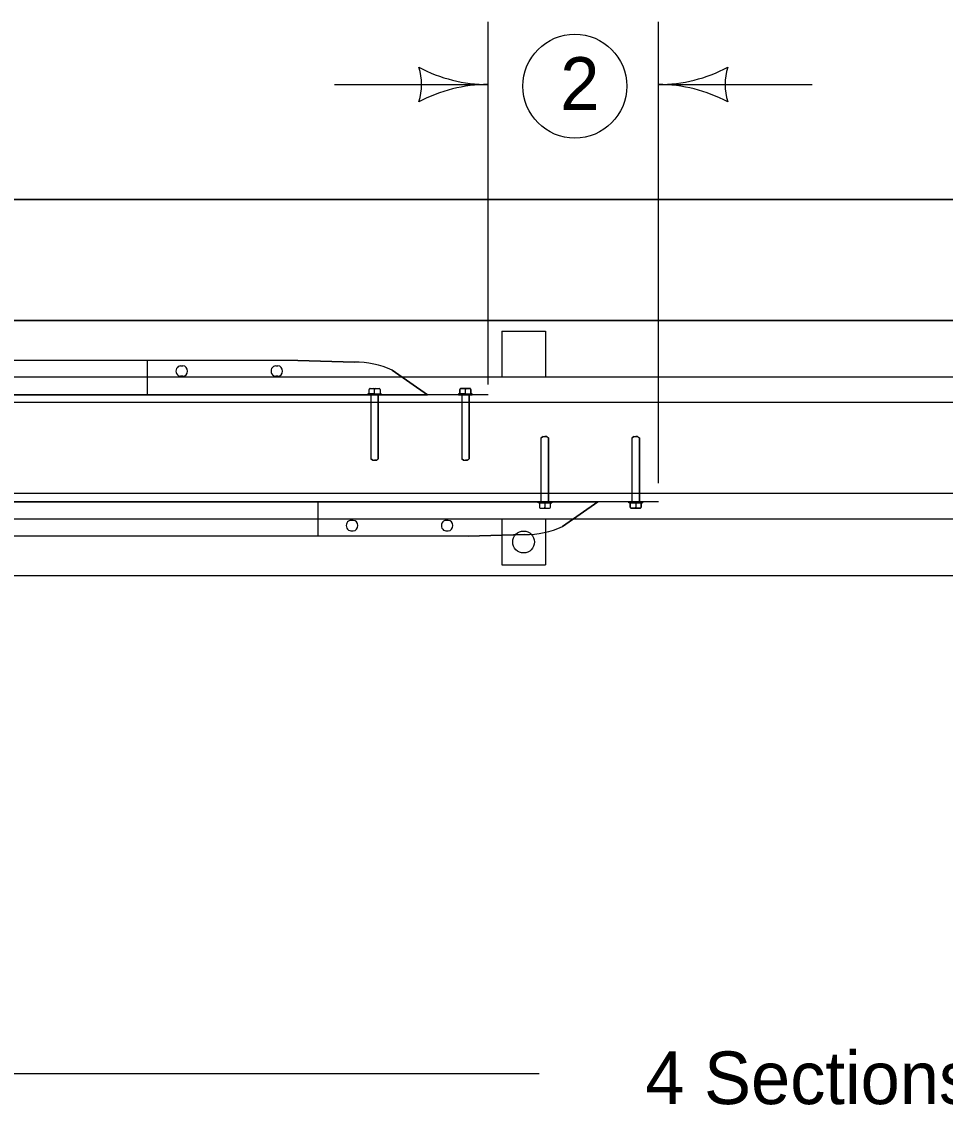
# Model space of a CAD drawing. Extents: x 10028 to 81668, y 3581 to 11018.
# Drawn here: x 21470.5 to 21736.9, y 8565.3 to 8882.3 of the extents above; entities that cross this region are included whole.
import ezdxf

# ---------------------------------------------------------------- set-up
doc = ezdxf.new("R2010")
doc.units = 0
for name, color, linetype in [('conPaving', 7, 'Continuous'), ('dsnCellsNorthArrow', 7, 'Continuous'), ('dsnTextTabulation', 7, 'Continuous'), ('Level 41', 7, 'Continuous'), ('Level 9', 7, 'Continuous')]:
    doc.layers.add(name, color=color, linetype=linetype)

msp = doc.modelspace()

# ---------------------------------------------------------------- linework, layer by layer
at = {"layer": 'conPaving'}
for p, q in [((21550.11, 8784.52), (21265.03, 8784.52)), ((21516.25, 8782.98), (21516.92, 8782.98)), ((21543.68, 8782.98), (21544.34, 8782.98)), ((21566.42, 8784.09), (21550.11, 8784.52)), ((21587.51, 8774.62), (21577.26, 8781.76)), ((21516.92, 8780.01), (21516.25, 8780.01)), ((21544.34, 8780.01), (21543.68, 8780.01)), ((21596.85, 8776.17), (21596.85, 8774.91)), ((21598.72, 8776.48), (21597.13, 8776.48)), ((21599.75, 8776.48), (21598.72, 8776.48)), ((21600.03, 8774.91), (21600.03, 8776.17)), ((21243.97, 8774.62), (21571.16, 8774.62)), ((21571.16, 8774.62), (21571.16, 8756.13)), ((21573.29, 8756.13), (21573.29, 8774.62)), ((21573.29, 8774.62), (21587.51, 8774.62)), ((21596.85, 8774.91), (21596.45, 8774.91)), ((21596.45, 8774.91), (21596.45, 8774.62)), ((21596.45, 8774.62), (21597.38, 8774.62)), ((21597.38, 8774.62), (21597.38, 8756.13)), ((21599.5, 8756.13), (21599.5, 8774.62)), ((21599.5, 8774.62), (21600.43, 8774.62)), ((21600.43, 8774.91), (21600.03, 8774.91)), ((21600.43, 8774.62), (21600.43, 8774.91)), ((21620.32, 8762.26), (21620.85, 8762.65)), ((21620.85, 8762.65), (21621.38, 8762.65)), ((21621.38, 8762.65), (21621.91, 8762.65)), ((21621.91, 8762.65), (21622.44, 8762.26)), ((21646.53, 8762.26), (21647.06, 8762.65)), ((21647.06, 8762.65), (21647.59, 8762.65)), ((21647.59, 8762.65), (21648.12, 8762.65)), ((21648.12, 8762.65), (21648.65, 8762.26)), ((21620.32, 8743.77), (21620.32, 8762.26)), ((21622.44, 8762.26), (21622.44, 8743.77)), ((21646.53, 8743.77), (21646.53, 8762.26)), ((21648.65, 8762.26), (21648.65, 8743.77)), ((21571.16, 8756.13), (21571.7, 8755.74)), ((21571.7, 8755.74), (21572.23, 8755.74)), ((21572.23, 8755.74), (21572.76, 8755.74)), ((21572.76, 8755.74), (21573.29, 8756.13)), ((21597.38, 8756.13), (21597.91, 8755.74)), ((21597.91, 8755.74), (21598.44, 8755.74)), ((21598.44, 8755.74), (21598.97, 8755.74)), ((21598.97, 8755.74), (21599.5, 8756.13)), ((21293.12, 8743.77), (21620.32, 8743.77)), ((21622.44, 8743.77), (21636.66, 8743.77)), ((21636.66, 8743.77), (21626.41, 8736.63)), ((21645.6, 8743.48), (21645.6, 8743.77)), ((21645.6, 8743.77), (21646.53, 8743.77)), ((21648.65, 8743.77), (21649.58, 8743.77)), ((21649.58, 8743.77), (21649.58, 8743.48)), ((21646, 8743.48), (21645.6, 8743.48)), ((21646, 8742.22), (21646, 8743.48)), ((21647.88, 8741.91), (21646.28, 8741.91)), ((21648.9, 8741.91), (21647.88, 8741.91)), ((21649.58, 8743.48), (21649.19, 8743.48)), ((21649.19, 8743.48), (21649.19, 8742.22)), ((21566.07, 8738.38), (21565.4, 8738.38)), ((21593.5, 8738.38), (21592.83, 8738.38)), ((21565.4, 8735.41), (21566.07, 8735.41)), ((21592.83, 8735.41), (21593.5, 8735.41)), ((21615.58, 8734.3), (21599.26, 8733.87)), ((21599.26, 8733.87), (21314.18, 8733.87))]:
    msp.add_line(p, q, dxfattribs=at)
for centre, major_axis, ratio, start_param, end_param in [((21516.25, 8781.5), (0, 1.49), 0.899999, 0, 3.141593), ((21516.92, 8781.5), (0, 1.49), 0.899999, 3.141593, 6.283185), ((21543.68, 8781.5), (0, 1.49), 0.899999, 0, 3.141593), ((21544.34, 8781.5), (0, 1.49), 0.899999, 3.141593, 6.283185), ((21566.42, 8758.56), (25.97, 0), 0.98332, 1.140354, 1.570796), ((21597.13, 8776.17), (0, -0.315), 0.899999, 3.141593, 4.712389), ((21599.75, 8776.17), (0, -0.315), 0.899999, 1.570796, 3.141593), ((21646.28, 8742.22), (0, -0.315), 0.899999, 4.712389, 6.283185), ((21648.9, 8742.22), (0, -0.315), 0.899999, 6.283185, 7.853982), ((21565.4, 8736.89), (0, 1.49), 0.899999, 0, 3.141593), ((21566.07, 8736.89), (0, 1.49), 0.899999, 3.141593, 6.283185), ((21592.83, 8736.89), (0, 1.49), 0.899999, 0, 3.141593), ((21593.5, 8736.89), (0, 1.49), 0.899999, 3.141593, 6.283185), ((21615.58, 8759.83), (25.97, 0), 0.98332, 4.712389, 5.142831)]:
    msp.add_ellipse(centre, major_axis=major_axis, ratio=ratio, start_param=start_param, end_param=end_param, dxfattribs=at)
at = {"layer": 'dsnTextTabulation'}
for p, q in [((21604.99, 8777.61), (21604.99, 8882.25)), ((21654.15, 8749.1), (21654.15, 8882.25)), ((21560.62, 8864.19), (21605, 8864.19)), ((21654.15, 8864.19), (21698.52, 8864.19)), ((21860.99, 8796.14), (21369.47, 8796.14)), ((21860.99, 8779.76), (21369.47, 8779.76)), ((21860.99, 8772.38), (21369.47, 8772.38)), ((21860.99, 8746.17), (21369.47, 8746.17)), ((21860.99, 8738.8), (21369.47, 8738.8)), ((21860.99, 8722.41), (21369.47, 8722.41)), ((21364.12, 8578.73), (21619.77, 8578.73))]:
    msp.add_line(p, q, dxfattribs=at)
msp.add_circle((21630.02, 8863.73), 15, dxfattribs=at)
for centre, radius, start, end in [((21569.36, 8864.19), 16.42, 342.2666, 17.7333), ((21605, 8906.69), 42.5, 241.9275, 270), ((21569.36, 8864.19), 16.42, 342.2666, 17.7333), ((21605, 8906.69), 42.5, 241.9275, 270), ((21654.15, 8906.69), 42.5, 270, 298.0725), ((21654.15, 8906.69), 42.5, 270, 298.0725), ((21689.78, 8864.19), 16.42, 162.2666, 197.7334), ((21689.78, 8864.19), 16.42, 162.2666, 197.7334), ((21605, 8821.69), 42.5, 90, 118.0725), ((21605, 8821.69), 42.5, 90, 118.0725), ((21654.15, 8821.69), 42.5, 61.9275, 90), ((21654.15, 8821.69), 42.5, 61.9275, 90)]:
    msp.add_arc(centre, radius, start, end, dxfattribs=at)
at = {"layer": 'Level 41'}
for p, q in [((21608.94, 8793.02), (21621.52, 8793.02)), ((21608.94, 8793.02), (21608.94, 8779.76)), ((21621.52, 8793.02), (21621.52, 8779.76)), ((21608.94, 8738.8), (21608.94, 8725.54)), ((21621.52, 8738.8), (21621.52, 8725.54)), ((21608.94, 8725.54), (21621.52, 8725.54))]:
    msp.add_line(p, q, dxfattribs=at)
msp.add_circle((21615.23, 8732.17), 3.15, dxfattribs=at)
at = {"layer": 'Level 9'}
for p, q in [((21357.59, 8831.02), (23377.13, 8831.02)), ((21857.99, 8831.02), (21448.05, 8831.02)), ((21448.05, 8796.14), (21860.99, 8796.14)), ((21550.11, 8784.52), (21265.03, 8784.52)), ((21506.69, 8774.62), (21506.69, 8784.52)), ((21570.63, 8774.91), (21570.63, 8776.17)), ((21570.92, 8776.48), (21571.94, 8776.48)), ((21571.94, 8776.48), (21573.54, 8776.48)), ((21572.23, 8774.91), (21572.23, 8776.17)), ((21573.82, 8776.17), (21573.82, 8774.91)), ((21596.85, 8774.91), (21596.85, 8776.17)), ((21597.13, 8776.48), (21598.16, 8776.48)), ((21598.16, 8776.48), (21599.75, 8776.48)), ((21598.44, 8774.91), (21598.44, 8776.17)), ((21600.03, 8776.17), (21600.03, 8774.91)), ((21604.99, 8774.62), (21210.14, 8774.62)), ((21572.23, 8774.91), (21570.24, 8774.91)), ((21570.24, 8774.91), (21570.24, 8774.62)), ((21570.24, 8774.62), (21574.22, 8774.62)), ((21570.63, 8774.91), (21573.82, 8774.91)), ((21571.16, 8774.62), (21571.16, 8756.13)), ((21572.23, 8774.91), (21574.22, 8774.91)), ((21572.23, 8774.62), (21573.29, 8774.62)), ((21573.29, 8774.62), (21573.29, 8756.13)), ((21574.22, 8774.62), (21574.22, 8774.91)), ((21598.44, 8774.91), (21596.45, 8774.91)), ((21596.45, 8774.91), (21596.45, 8774.62)), ((21596.45, 8774.62), (21600.43, 8774.62)), ((21596.85, 8774.91), (21600.03, 8774.91)), ((21597.38, 8774.62), (21597.38, 8756.13)), ((21598.44, 8774.91), (21600.43, 8774.91)), ((21598.44, 8774.62), (21599.5, 8774.62)), ((21599.5, 8774.62), (21599.5, 8756.13)), ((21600.43, 8774.62), (21600.43, 8774.91)), ((21620.85, 8762.65), (21620.32, 8762.26)), ((21620.85, 8762.65), (21621.38, 8762.65)), ((21621.91, 8762.65), (21621.38, 8762.65)), ((21621.91, 8762.65), (21622.44, 8762.26)), ((21647.06, 8762.65), (21646.53, 8762.26)), ((21647.06, 8762.65), (21647.59, 8762.65)), ((21648.12, 8762.65), (21647.59, 8762.65)), ((21648.12, 8762.65), (21648.65, 8762.26)), ((21620.32, 8743.77), (21620.32, 8762.26)), ((21622.44, 8743.77), (21622.44, 8762.26)), ((21646.53, 8743.77), (21646.53, 8762.26)), ((21648.65, 8743.77), (21648.65, 8762.26)), ((21571.7, 8755.74), (21571.16, 8756.13)), ((21571.7, 8755.74), (21572.23, 8755.74)), ((21572.76, 8755.74), (21572.23, 8755.74)), ((21572.76, 8755.74), (21573.29, 8756.13)), ((21597.91, 8755.74), (21597.38, 8756.13)), ((21597.91, 8755.74), (21598.44, 8755.74)), ((21598.97, 8755.74), (21598.44, 8755.74)), ((21598.97, 8755.74), (21599.5, 8756.13)), ((21654.15, 8743.77), (21259.29, 8743.77)), ((21555.84, 8743.77), (21555.84, 8733.87)), ((21619.39, 8743.48), (21619.39, 8743.77)), ((21619.39, 8743.77), (21623.37, 8743.77)), ((21621.38, 8743.77), (21622.44, 8743.77)), ((21623.37, 8743.77), (21623.37, 8743.48)), ((21645.6, 8743.48), (21645.6, 8743.77)), ((21645.6, 8743.77), (21649.58, 8743.77)), ((21647.59, 8743.77), (21648.65, 8743.77)), ((21649.58, 8743.77), (21649.58, 8743.48)), ((21621.38, 8743.48), (21619.39, 8743.48)), ((21619.79, 8743.48), (21622.97, 8743.48)), ((21619.79, 8743.48), (21619.79, 8742.22)), ((21620.07, 8741.91), (21621.1, 8741.91)), ((21621.1, 8741.91), (21622.69, 8741.91)), ((21621.38, 8743.48), (21623.37, 8743.48)), ((21621.38, 8743.48), (21621.38, 8742.22)), ((21622.97, 8742.22), (21622.97, 8743.48)), ((21647.59, 8743.48), (21645.6, 8743.48)), ((21646, 8743.48), (21649.19, 8743.48)), ((21646, 8743.48), (21646, 8742.22)), ((21646.28, 8741.91), (21647.31, 8741.91)), ((21647.31, 8741.91), (21648.9, 8741.91)), ((21647.59, 8743.48), (21649.58, 8743.48)), ((21647.59, 8743.48), (21647.59, 8742.22)), ((21649.19, 8742.22), (21649.19, 8743.48)), ((21599.26, 8733.87), (21314.18, 8733.87))]:
    msp.add_line(p, q, dxfattribs=at)
for points in [[(21516.25, 8782.98), (21516.92, 8782.98)], [(21543.68, 8782.98), (21544.34, 8782.98)], [(21550.11, 8784.52), (21566.42, 8784.09)], [(21577.26, 8781.76), (21587.51, 8774.62)], [(21516.92, 8780.01), (21516.25, 8780.01)], [(21544.34, 8780.01), (21543.68, 8780.01)], [(21626.41, 8736.63), (21636.66, 8743.77)], [(21566.07, 8738.38), (21565.4, 8738.38)], [(21593.5, 8738.38), (21592.83, 8738.38)], [(21565.4, 8735.41), (21566.07, 8735.41)], [(21592.83, 8735.41), (21593.5, 8735.41)], [(21599.26, 8733.87), (21615.58, 8734.3)]]:
    msp.add_lwpolyline(points, dxfattribs=at)
for centre, major_axis, ratio, start_param, end_param in [((21516.25, 8781.5), (0, 1.49), 0.899999, 0, 3.141593), ((21516.92, 8781.5), (0, 1.49), 0.899999, 3.141593, 6.283185), ((21543.68, 8781.5), (0, 1.49), 0.899999, 0, 3.141593), ((21544.34, 8781.5), (0, 1.49), 0.899999, 3.141593, 6.283185), ((21566.42, 8758.56), (25.97, 0), 0.98332, 1.140354, 1.570796), ((21570.92, 8776.17), (0, 0.315), 0.899999, 6.283185, 7.853982), ((21571.94, 8776.17), (0, 0.315), 0.899999, 4.712389, 6.283185), ((21572.51, 8776.17), (0, 0.315), 0.899999, 0, 1.570796), ((21573.54, 8776.17), (0, 0.315), 0.899999, 4.712389, 6.283185), ((21597.13, 8776.17), (0, 0.315), 0.899999, 6.283185, 7.853982), ((21598.16, 8776.17), (0, 0.315), 0.899999, 4.712389, 6.283185), ((21598.72, 8776.17), (0, 0.315), 0.899999, 0, 1.570796), ((21599.75, 8776.17), (0, 0.315), 0.899999, 4.712389, 6.283185), ((21620.07, 8742.22), (0, 0.315), 0.899999, 1.570796, 3.141593), ((21621.1, 8742.22), (0, 0.315), 0.899999, 3.141593, 4.712389), ((21621.66, 8742.22), (0, 0.315), 0.899999, 1.570796, 3.141593), ((21622.69, 8742.22), (0, 0.315), 0.899999, 3.141593, 4.712389), ((21646.28, 8742.22), (0, 0.315), 0.899999, 1.570796, 3.141593), ((21647.31, 8742.22), (0, 0.315), 0.899999, 3.141593, 4.712389), ((21647.88, 8742.22), (0, 0.315), 0.899999, 1.570796, 3.141593), ((21648.9, 8742.22), (0, 0.315), 0.899999, 3.141593, 4.712389), ((21565.4, 8736.89), (0, 1.49), 0.899999, 0, 3.141593), ((21566.07, 8736.89), (0, 1.49), 0.899999, 3.141593, 6.283185), ((21592.83, 8736.89), (0, 1.49), 0.899999, 0, 3.141593), ((21593.5, 8736.89), (0, 1.49), 0.899999, 3.141593, 6.283185), ((21615.58, 8759.83), (25.97, 0), 0.98332, 4.712389, 5.142831)]:
    msp.add_ellipse(centre, major_axis=major_axis, ratio=ratio, start_param=start_param, end_param=end_param, dxfattribs=at)

# ---------------------------------------------------------------- texts
at = {"layer": 'dsnCellsNorthArrow'}
msp.add_text('4 Sections Anchored Temporary Barrier Rail, Concrete', height=15.2, dxfattribs=at).set_placement((21650.36, 8569.93))
at = {"layer": 'dsnTextTabulation'}
msp.add_text('2', height=15.2, dxfattribs=at).set_placement((21625.81, 8856.89))

doc.saveas('drawing.dxf')
